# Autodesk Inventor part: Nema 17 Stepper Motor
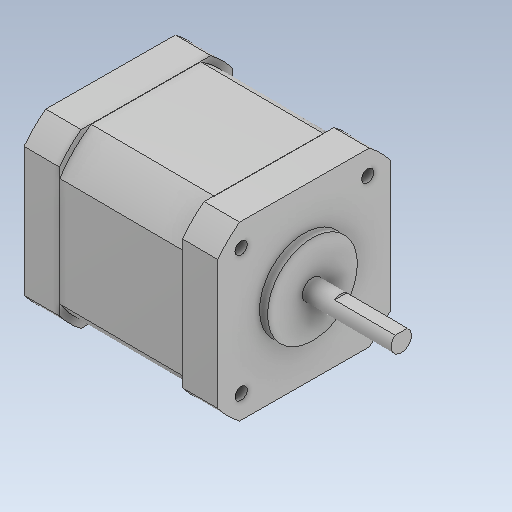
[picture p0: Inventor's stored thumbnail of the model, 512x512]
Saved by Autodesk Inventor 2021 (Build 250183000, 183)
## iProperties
Created: 2026-10
Part Number: Nema 17 Stepper Motor
Material: Steel
Document SubType Name: Modeling
Designer: hp
Density: 7.85 g/cm^3
Appearance: Default
Author: hp
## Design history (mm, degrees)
feature "Body1"
body "Solid1"
